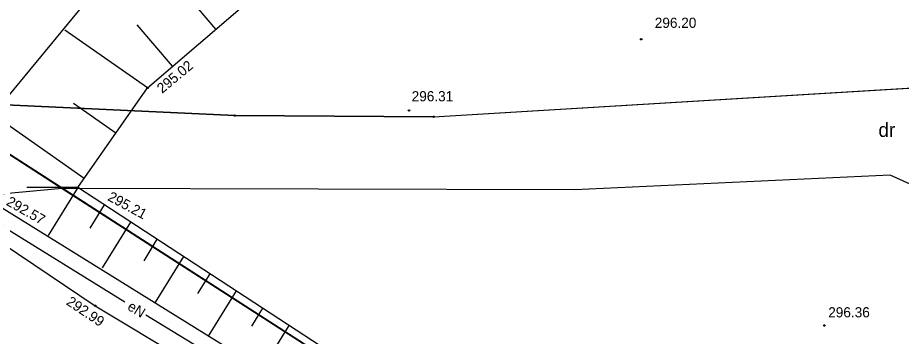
# Model space of a CAD drawing. Extents: x 7477803 to 7478145, y 5500698 to 5500984.
# Drawn here: x 7477935.9 to 7477995, y 5500903.1 to 5500924.5 of the extents above; entities that cross this region are included whole.
import ezdxf

# ---------------------------------------------------------------- set-up
doc = ezdxf.new("R2010")
doc.units = 0
for name, color, linetype in [('203-Punkt załamania granicy działki nie stabilizowany', 7, 'Continuous'), ('e_opisy', 7, 'Continuous'), ('eNN', 7, 'Continuous'), ('gr_dzialki', 7, 'Continuous'), ('gr_klasy', 7, 'Continuous'), ('gr_uzytek', 7, 'Continuous'), ('jezdnia', 7, 'Continuous'), ('opis_uzytek', 7, 'Continuous'), ('pkt_wys', 7, 'Continuous'), ('skarp_wypel', 7, 'Continuous'), ('skarpa_gora', 7, 'Continuous')]:
    doc.layers.add(name, color=color, linetype=linetype)

# ---------------------------------------------------------------- blocks, each defined once
blk = doc.blocks.new('203')
blk.add_circle((0, 0), 0.045)
blk = doc.blocks.new('801_5')
at = {"layer": 'pkt_wys'}
blk.add_circle((0, 0), 0.05, dxfattribs=at)
blk.add_circle((0, 0), 0.05, dxfattribs=at)

msp = doc.modelspace()

# ---------------------------------------------------------------- linework, layer by layer
at = {"layer": 'eNN'}
for points in [[(7477943.05, 5500905.439), (7477934.522, 5500910.702), (7477926.234, 5500915.963), (7477923.573, 5500917.637), (7477921.419, 5500919.298), (7477921.124, 5500919.558)], [(7478044.292, 5500829.332), (7478043.979, 5500830.08), (7478036.967, 5500842.126), (7478033.374, 5500847.92), (7478030.266, 5500851.792), (7478027.179, 5500855.154), (7478025.031, 5500856.9), (7478008.369, 5500866.572), (7477997.07, 5500873.297), (7477990.438, 5500877.31), (7477980.374, 5500883.358), (7477966.627, 5500891.122), (7477956.111, 5500897.36), (7477948.099, 5500902.324), (7477944.454, 5500904.573)]]:
    msp.add_lwpolyline(points, dxfattribs=at)
at = {"layer": 'gr_dzialki'}
for points in [[(7477963.71, 5500917.85), (7478011.06, 5500920.71)], [(7477950.4, 5500917.93), (7477929.78, 5500918.89)], [(7477967.16, 5500894.83), (7477929.78, 5500918.89)], [(7477963.71, 5500917.85), (7477950.4, 5500917.93)]]:
    msp.add_lwpolyline(points, dxfattribs=at)
at = {"layer": 'gr_klasy'}
for points in [[(7477963.71, 5500917.85), (7477998.73, 5500919.96)], [(7477929.78, 5500918.89), (7477950.4, 5500917.93)], [(7477950.4, 5500917.93), (7477963.71, 5500917.85)], [(7477994.27, 5500913.94), (7477973.16, 5500912.95)], [(7477997.16, 5500912.65), (7477994.27, 5500913.94)], [(7477973.16, 5500912.95), (7477938.86, 5500913.04)], [(7477938.86, 5500913.04), (7477967.16, 5500894.83)]]:
    msp.add_lwpolyline(points, dxfattribs=at)
at = {"layer": 'gr_uzytek'}
msp.add_lwpolyline([(7477929.78, 5500918.89), (7477938.86, 5500913.04), (7477909.89, 5500910.36)], dxfattribs=at)
at = {"layer": 'jezdnia'}
for points in [[(7477897.344, 5500935.024), (7477905.871, 5500928.923), (7477941.067, 5500905.192)], [(7477941.067, 5500905.192), (7477953.13, 5500897.937)]]:
    msp.add_lwpolyline(points, dxfattribs=at)
at = {"layer": 'skarp_wypel'}
for p, q in [((7477949.145, 5500923.722), (7477944.386, 5500929.265)), ((7477946.243, 5500921.229), (7477943.867, 5500923.995)), ((7477944.561, 5500919.785), (7477939.017, 5500923.658)), ((7477942.442, 5500916.752), (7477939.605, 5500918.734)), ((7477940.323, 5500913.719), (7477934.46, 5500917.814)), ((7477939.898, 5500913.11), (7477936.474, 5500913.107)), ((7477939.898, 5500913.11), (7477937.913, 5500909.89)), ((7477941.664, 5500911.956), (7477940.702, 5500910.396)), ((7477943.429, 5500910.802), (7477941.532, 5500907.724)), ((7477945.195, 5500909.648), (7477944.307, 5500908.208)), ((7477946.96, 5500908.494), (7477945.048, 5500905.392)), ((7477948.726, 5500907.34), (7477947.911, 5500906.019)), ((7477950.491, 5500906.186), (7477948.631, 5500903.169)), ((7477952.257, 5500905.032), (7477951.516, 5500903.831)), ((7477954.022, 5500903.878), (7477952.214, 5500900.945))]:
    msp.add_line(p, q, dxfattribs=at)
at = {"layer": 'skarpa_gora'}
for points in [[(7478007.879, 5500866.795), (7478009.357, 5500868.166), (7477985.351, 5500883.4), (7477939.898, 5500913.11), (7477944.561, 5500919.785), (7477954.951, 5500928.707), (7477971.014, 5500935.434), (7477981.218, 5500940.405), (7477991.643, 5500944.907), (7477994.866, 5500942.92), (7478002.778, 5500931.769), (7478021.266, 5500905.519), (7478029.289, 5500903.308), (7478032.779, 5500894.332), (7478047.773, 5500881.148)], [(7478007.879, 5500866.795), (7477984.093, 5500881.159), (7477934.83, 5500911.735), (7477933.524, 5500917.153), (7477941.313, 5500926.602), (7477947.253, 5500931.749), (7477948.257, 5500932.619)]]:
    msp.add_lwpolyline(points, dxfattribs=at)

# ---------------------------------------------------------------- block references
at = {"layer": '203-Punkt załamania granicy działki nie stabilizowany'}
for p in [(7477950.4, 5500917.93), (7477963.71, 5500917.85)]:
    msp.add_blockref('203', p, dxfattribs=at)
at = {"layer": 'pkt_wys', "rotation": 0.0626175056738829}
for p in [(7477977.607, 5500923.041), (7477944.561, 5500919.785), (7477962.062, 5500918.274), (7477939.898, 5500913.11), (7477941.067, 5500905.192), (7477989.868, 5500903.875)]:
    msp.add_blockref('801_5', p, dxfattribs=at)

# ---------------------------------------------------------------- texts
at = {"layer": 'e_opisy'}
msp.add_text('eN', height=0.68, rotation=328.3239, dxfattribs=at).set_placement((7477943.161, 5500904.971))
at = {"layer": 'opis_uzytek'}
msp.add_text('dr', height=0.94, dxfattribs=at).set_placement((7477993.49, 5500916.5))
at = {"layer": 'pkt_wys'}
for s, rotation, p in [('296.20', 0.06262, (7477978.518, 5500923.8)), ('295.02', 39.78872, (7477945.543, 5500919.378)), ('296.31', 0.06262, (7477962.245, 5500918.882)), ('295.21', 331.59746, (7477941.839, 5500912.286)), ('292.57', 330.21267, (7477935.05, 5500911.975)), ('292.99', 326.06074, (7477939.07, 5500905.316)), ('296.36', 0.06262, (7477990.128, 5500904.416))]:
    msp.add_text(s, height=0.68, rotation=rotation, dxfattribs=at).set_placement(p)

doc.saveas('drawing.dxf')
